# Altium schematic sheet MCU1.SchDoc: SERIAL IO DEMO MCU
size A4; Engineer: SRKH; DocumentNumber: 2; Revision: 1.00; SheetNumber: 2; SheetTotal: 7
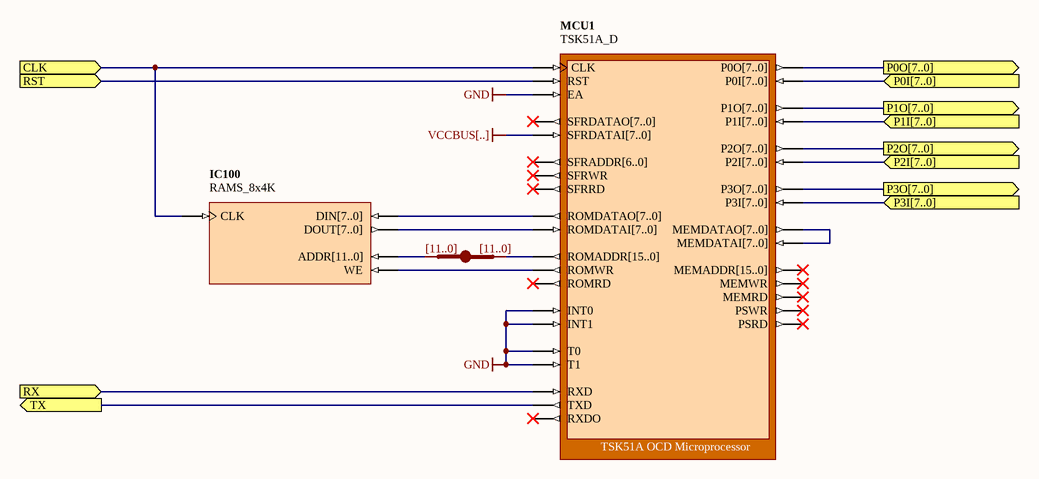
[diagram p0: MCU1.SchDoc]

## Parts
IC100  RAMS_8x4K
JB_S1  IndexA: [11..0]  (hidden comment: JB)
MCU1  TSK51A_D

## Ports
CLK (in), P0I[7..0] (in), P0O[7..0] (out), P1I[7..0] (in), P1O[7..0] (out), P2I[7..0] (in), P2O[7..0] (out), P3I[7..0] (in), P3O[7..0] (out), RST (in), RX (in), TX (out)

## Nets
GND: MCU1.EA MCU1.INT0 MCU1.INT1 MCU1.T0 MCU1.T1
CLK: IC100.CLK MCU1.CLK ; port CLK
RST: MCU1.RST ; port RST
RX: MCU1.RXD ; port RX
TX: MCU1.TXD ; port TX
NetIC100_WE: IC100.WE MCU1.ROMWR

Not connected (* = marked no-connect by the designer): IC100 ADDR[11..0] DIN[7..0] DOUT[7..0]; JB_S1 A[0..0] B[0..0]; MCU1 MEMADDR[15..0]* MEMDATAI[7..0] MEMDATAO[7..0] MEMRD* MEMWR* P0I[7..0] P0O[7..0] P1I[7..0] P1O[7..0] P2I[7..0] P2O[7..0] P3I[7..0] P3O[7..0] PSRD* PSWR* ROMADDR[15..0] ROMDATAI[7..0] ROMDATAO[7..0] ROMRD* RXDO* SFRADDR[6..0]* SFRDATAI[7..0] SFRDATAO[7..0]* SFRRD* SFRWR*

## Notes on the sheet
- Labels drawn without touching a wire or pin: VCCBUS[..]

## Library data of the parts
IC100 = RAMS_8x4K: Single Port RAM; Memory_Depth: 4096; Memory_Type: RAM_SinglePortBlock; Memory_Width: 8; Memory_ClockEdge: Rising; Nexus_Core: Memory_Program; Memory_EnablePin: False
JB_S1 = JB: System BUS Joiner
MCU1 = TSK51A_D: TSK51A OCD Microprocessor; NEXUS_CORE: Processor_OCDS; NEXUS_JTAG_DEVICE: True; NEXUS_JTAG_ORDER: 0; ChildModel1: RAM256x8_TSK51D; ChildCore1: M1; Memory_Configuration: Record[NEXUS_CORE]{}ComponentDesignator[iram]{}Memory_Depth[256]{}Memory_UsageType[ram]{}ProgramDownloadAddress[0x0]{}Memory_BusType[c51:idata_bus]{n}Record[NEXUS_CORE]{}ComponentDesignator[xram]{}Memory_Depth[64k]{}Memory_UsageType[ram]{}ProgramDownloadAddress[0x0]{}Memory_BusType[c51:xdata_bus]{n}Record[NEXUS_CORE]{}ComponentDesignator[xrom]{}Memory_Depth[64k]{}Memory_UsageType[rom]{}ProgramDownloadAddress[0x0]{}Memory_BusType[c51:code_bus]{n}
